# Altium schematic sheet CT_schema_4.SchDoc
size 298 x 247 mm
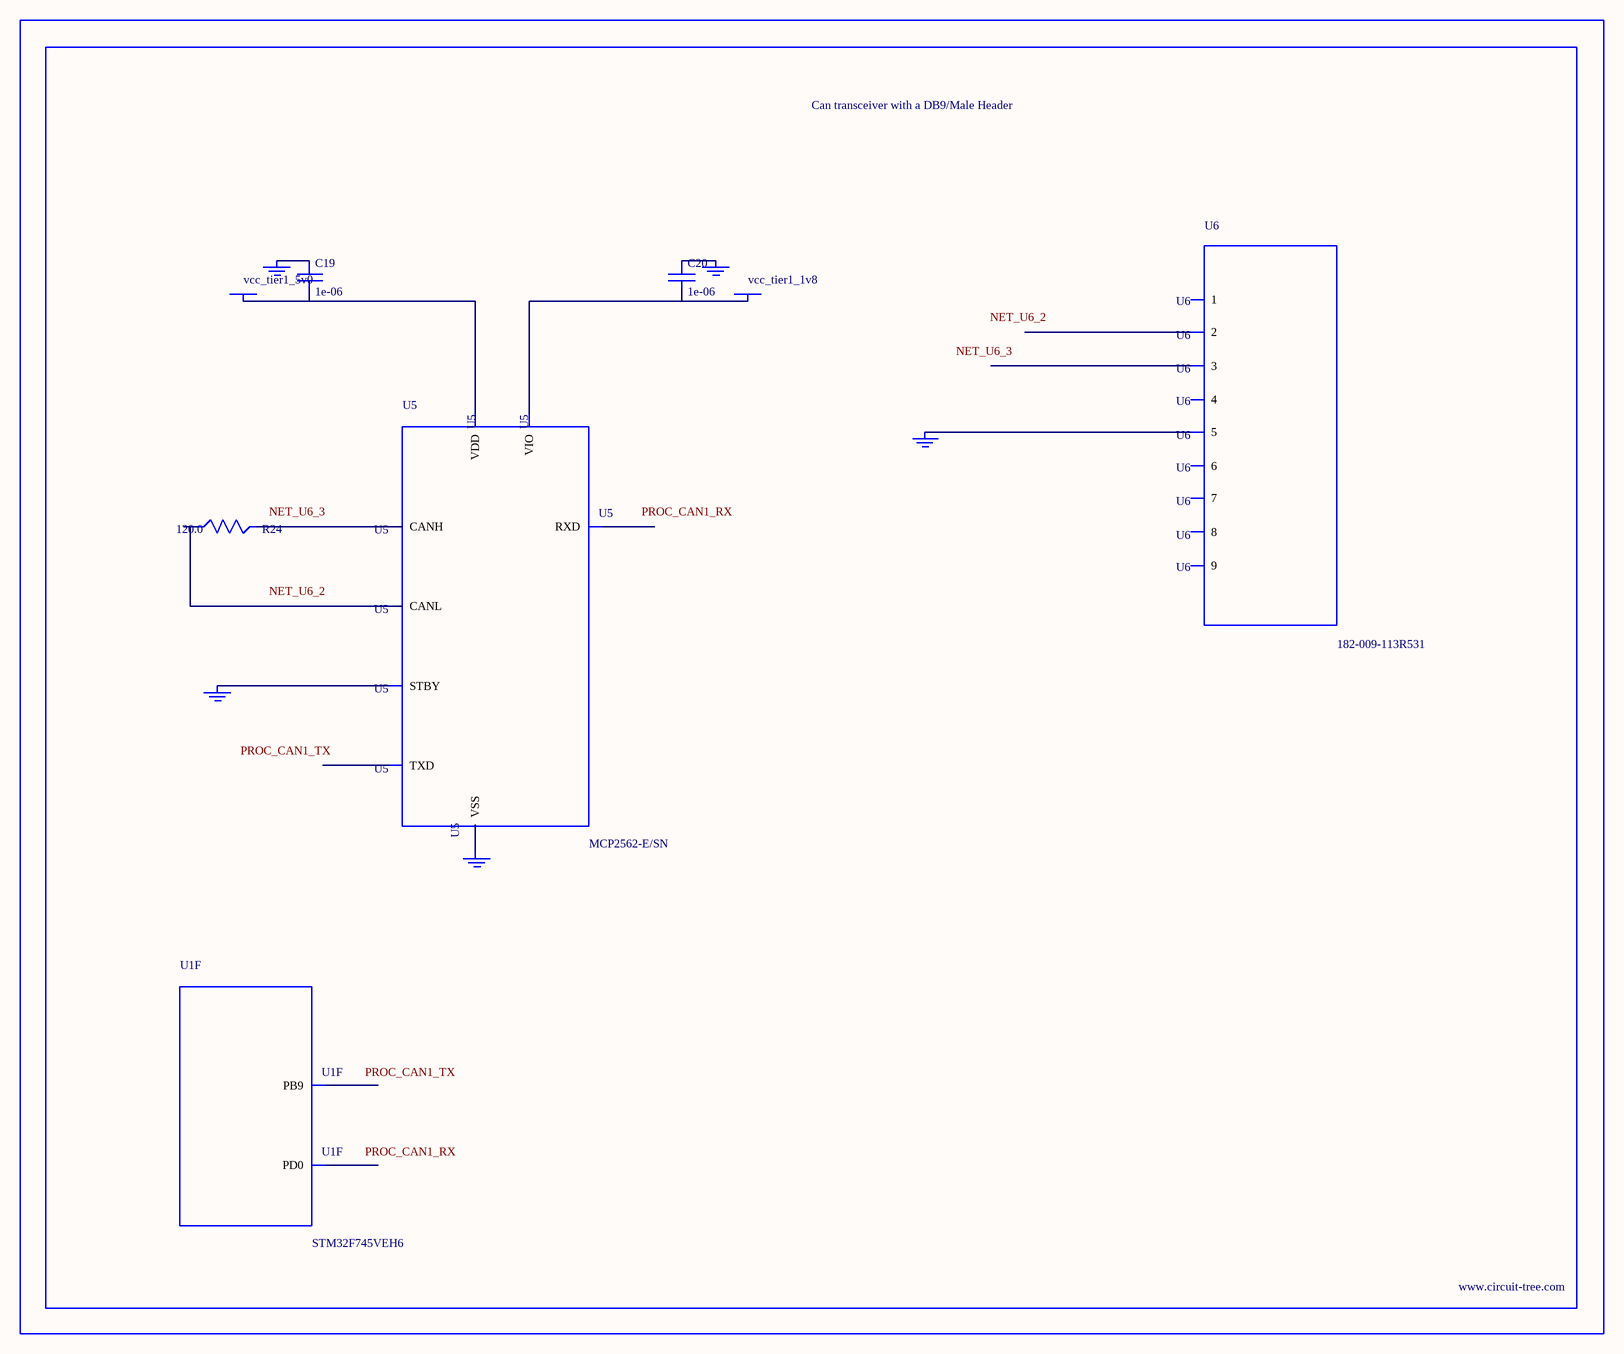
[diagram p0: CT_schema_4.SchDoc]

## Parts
BORDER3  (no value)
C19  1e-06  [C0603]
C20  1e-06  [C0603]
GND_INSTANCE_3_0  (no value)
GND_INSTANCE_3_1  (no value)
GND_INSTANCE_3_2  (no value)
GND_INSTANCE_3_3  (no value)
GND_INSTANCE_3_4  (no value)
POWER_INSTANCE_3_0  vcc_tier1_5v0
POWER_INSTANCE_3_1  vcc_tier1_1v8
R24  120.0  [R0603]
U1  STM32F745VEH6  [TFBGA100]  (part F of 10)
U5  MCP2562-E/SN  [SOIC-8]
U6  182-009-113R531  [182-009-MALE]

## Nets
NetC19_1: C19.1 GND_INSTANCE_3_0.0(GND)
NetC19_2: C19.2 POWER_INSTANCE_3_0.0(PWR) U5.3(VDD)
NetC20_1: C20.1 GND_INSTANCE_3_1.0(GND)
NetC20_2: C20.2 POWER_INSTANCE_3_1.0(PWR) U5.5(VIO)
NetGND_INSTANCE_3_2_0: GND_INSTANCE_3_2.0(GND) U5.8(STBY)
NetGND_INSTANCE_3_3_0: GND_INSTANCE_3_3.0(GND) U5.2(VSS)
NetGND_INSTANCE_3_4_0: GND_INSTANCE_3_4.0(GND) U6.5
NetR24_1: R24.1 U5.6(CANL)
NetR24_2: R24.2 U5.7(CANH)

Not connected (* = marked no-connect by the designer): U1 A4(PB9) D8(PD0); U5 1(TXD) 4(RXD); U6 1 2 3 4 6 7 8 9

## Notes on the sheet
- Labels drawn without touching a wire or pin: NET_U6_2, NET_U6_3, PROC_CAN1_RX, PROC_CAN1_TX

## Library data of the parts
BORDER3 = BORDER_PAGE3
C19 C20 = C0603C105K3RACTU
GND_INSTANCE_3_0-GND_INSTANCE_3_4 = GND
POWER_INSTANCE_3_0 POWER_INSTANCE_3_1 = PWR
R24 = RC0603JR-07120RL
